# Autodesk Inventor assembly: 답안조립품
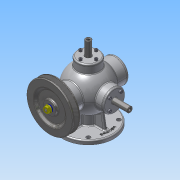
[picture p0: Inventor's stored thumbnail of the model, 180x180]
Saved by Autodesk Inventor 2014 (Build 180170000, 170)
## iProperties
Created: 2016-01
Part Number: 답안조립품
Document SubType Name: Assembly
Designer: Administrator
Mass: 3770.67 g
Surface Area: 2410.99 cm^2
Volume: 903.657 cm^3
Density: 4.17267 g/cm^3
Author: Administrator
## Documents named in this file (17)
- C:\Users\Administrator\Desktop\360108V1017\답안조립품.iam
- C:\Users\Administrator\Desktop\360108V1017\본체.ipt
- C:\Users\Administrator\Desktop\360108V1017\V-벨트풀리.ipt
- C:\Users\Administrator\Desktop\360108V1017\너트-M8x1.ipt
- C:\Users\Administrator\Desktop\360108V1017\뒤커버.ipt
- C:\Users\Administrator\Desktop\360108V1017\베어링- 6202.ipt
- C:\Users\Administrator\Desktop\360108V1017\본체커버.ipt
- C:\Users\Administrator\Desktop\360108V1017\볼트 M4x0.7.ipt
- C:\Users\Administrator\Desktop\360108V1017\스프링1.ipt
- C:\Users\Administrator\Desktop\360108V1017\스프링2.ipt
- C:\Users\Administrator\Desktop\360108V1017\슬라이드 커버.ipt
- C:\Users\Administrator\Desktop\360108V1017\슬라이드.ipt
- C:\Users\Administrator\Desktop\360108V1017\앞커버.ipt
- C:\Users\Administrator\Desktop\360108V1017\오일실.ipt
- C:\Users\Administrator\Desktop\360108V1017\와셔 8x17.ipt
- C:\Users\Administrator\Desktop\360108V1017\축.ipt
- C:\Users\Administrator\Desktop\360108V1017\키-4x4.ipt
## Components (18 placed, 2 different names)
1. V-벨트풀리:1 — 플러쉬:18, 각도:2
2. M4x0.7x12:1
3. M4x0.7x12:2
4. M4x0.7x12:6
5. M4x0.7x12:7
6. M4x0.7x12:8
7. M4x0.7x12:3
8. M4x0.7x12:9
9. M4x0.7x12:10
10. M4x0.7x12:11
11. M4x0.7x12:4
12. M4x0.7x12:12
13. M4x0.7x12:13
14. M4x0.7x12:14
15. M4x0.7x12:5
16. M4x0.7x12:15
17. M4x0.7x12:16
18. M4x0.7x12:17
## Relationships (2: Flush 1, Angle 1)
- 플러쉬:18 [Flush]: V-벨트풀리:1
- 각도:2 [Angle]: V-벨트풀리:1
